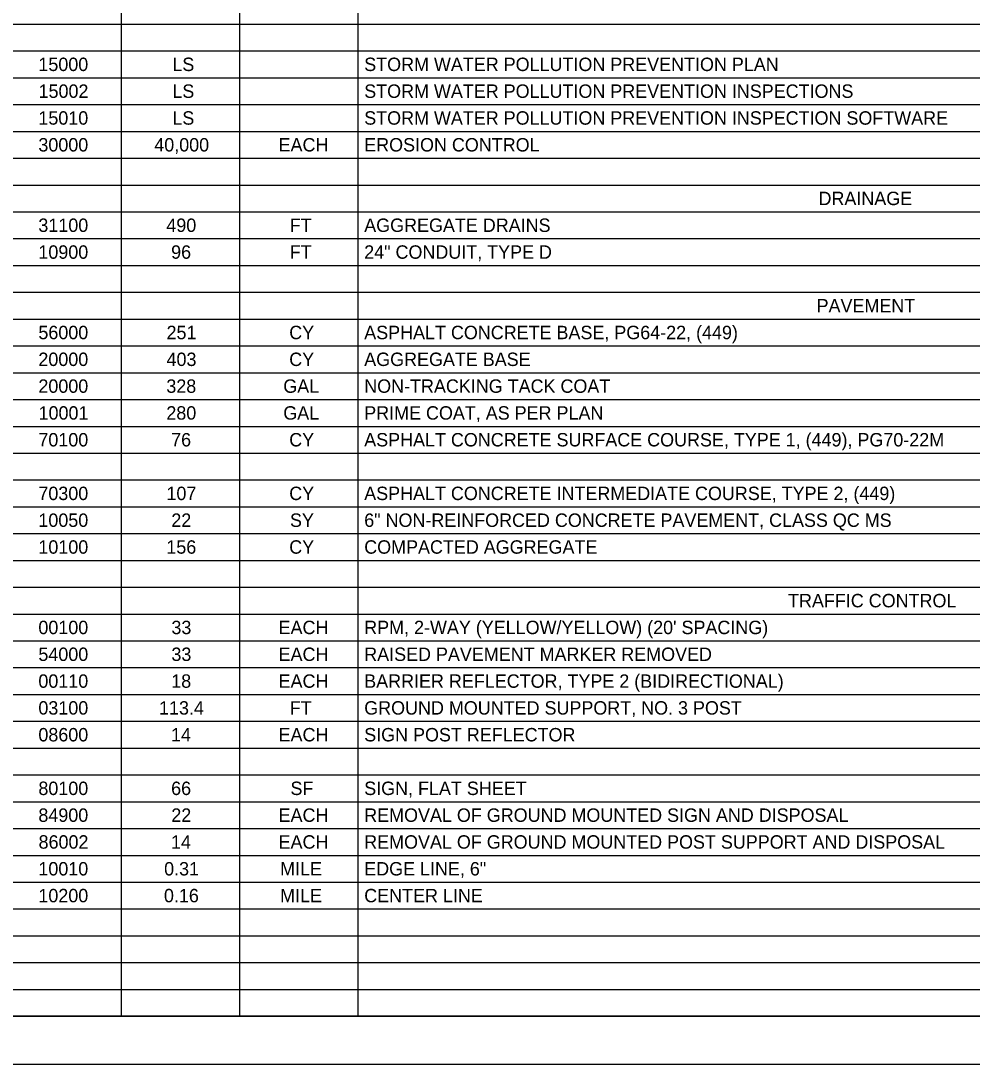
# Model space of a CAD drawing. Extents: x 0 to 34, y 0 to 22.
# Drawn here: x 16.99 to 26.92, y 0 to 10.89 of the extents above; entities that cross this region are included whole.
import ezdxf

# ---------------------------------------------------------------- set-up
doc = ezdxf.new("R2010")
doc.units = 0
for name, color, linetype in [('SH_Border', 7, 'Continuous'), ('SH_Cut_Line', 7, 'Continuous'), ('SH_Data', 7, 'Continuous'), ('SH_Text', 7, 'Continuous')]:
    doc.layers.add(name, color=color, linetype=linetype)

msp = doc.modelspace()

# ---------------------------------------------------------------- linework, layer by layer
at = {"layer": 'SH_Border'}
msp.add_lwpolyline([(1.5, 21.5), (33.5, 21.5), (33.5, 0.5), (1.5, 0.5)], close=True, dxfattribs=at)
at = {"layer": 'SH_Cut_Line'}
msp.add_lwpolyline([(0, 0), (34, 0), (34, 22), (0, 22)], close=True, dxfattribs=at)
at = {"layer": 'SH_Data'}
for p, q in [((18.036, 21.5), (18.036, 0.5)), ((19.272, 21.5), (19.272, 0.5)), ((20.507, 21.5), (20.507, 0.5)), ((1.5, 10.86), (32.004, 10.86)), ((1.5, 10.58), (32.004, 10.58)), ((1.5, 10.3), (32.004, 10.3)), ((1.5, 10.02), (32.004, 10.02)), ((1.5, 9.74), (32.004, 9.74)), ((1.5, 9.46), (32.004, 9.46)), ((1.5, 9.18), (32.004, 9.18)), ((1.5, 8.9), (32.004, 8.9)), ((1.5, 8.62), (32.004, 8.62)), ((1.5, 8.34), (32.004, 8.34)), ((1.5, 8.06), (32.004, 8.06)), ((1.5, 7.78), (32.004, 7.78)), ((1.5, 7.5), (32.004, 7.5)), ((1.5, 7.22), (32.004, 7.22)), ((1.5, 6.94), (32.004, 6.94)), ((1.5, 6.66), (32.004, 6.66)), ((1.5, 6.38), (32.004, 6.38)), ((1.5, 6.1), (32.004, 6.1)), ((1.5, 5.82), (32.004, 5.82)), ((1.5, 5.54), (32.004, 5.54)), ((1.5, 5.26), (32.004, 5.26)), ((1.5, 4.98), (32.004, 4.98)), ((1.5, 4.7), (32.004, 4.7)), ((1.5, 4.42), (32.004, 4.42)), ((1.5, 4.14), (32.004, 4.14)), ((1.5, 3.86), (32.004, 3.86)), ((1.5, 3.58), (32.004, 3.58)), ((1.5, 3.3), (32.004, 3.3)), ((1.5, 3.02), (32.004, 3.02)), ((1.5, 2.74), (32.004, 2.74)), ((1.5, 2.46), (32.004, 2.46)), ((1.5, 2.18), (32.004, 2.18)), ((1.5, 1.9), (32.004, 1.9)), ((1.5, 1.62), (32.004, 1.62)), ((1.5, 1.34), (32.004, 1.34)), ((1.5, 1.06), (32.004, 1.06)), ((1.5, 0.78), (32.004, 0.78)), ((1.5, 0.5), (32.004, 0.5))]:
    msp.add_line(p, q, dxfattribs=at)

# ---------------------------------------------------------------- texts
at = {"layer": 'SH_Text'}
for s, p in [('15000', (17.171, 10.37)), ('LS', (18.57, 10.37)), ('STORM WATER POLLUTION PREVENTION PLAN', (20.573, 10.37)), ('15002', (17.173, 10.09)), ('LS', (18.57, 10.09)), ('STORM WATER POLLUTION PREVENTION INSPECTIONS', (20.573, 10.09)), ('15010', (17.171, 9.81)), ('LS', (18.57, 9.81)), ('STORM WATER POLLUTION PREVENTION INSPECTION SOFTWARE', (20.573, 9.81)), ('30000', (17.171, 9.53)), ('40,000', (18.381, 9.53)), ('EACH', (19.679, 9.53)), ('EROSION CONTROL', (20.573, 9.53)), ('DRAINAGE', (25.316, 8.97)), ('31100', (17.171, 8.69)), ('490', (18.507, 8.69)), ('FT', (19.796, 8.69)), ('AGGREGATE DRAINS', (20.573, 8.69)), ('10900', (17.171, 8.41)), ('96', (18.557, 8.41)), ('FT', (19.796, 8.41)), ('24" CONDUIT, TYPE D', (20.573, 8.41)), ('PAVEMENT', (25.296, 7.85)), ('56000', (17.171, 7.57)), ('251', (18.509, 7.57)), ('CY', (19.79, 7.57)), ('ASPHALT CONCRETE BASE, PG64-22, (449)', (20.573, 7.57)), ('20000', (17.171, 7.29)), ('403', (18.509, 7.29)), ('CY', (19.79, 7.29)), ('AGGREGATE BASE', (20.573, 7.29)), ('20000', (17.171, 7.01)), ('328', (18.507, 7.01)), ('GAL', (19.728, 7.01)), ('NON-TRACKING TACK COAT', (20.573, 7.01)), ('10001', (17.173, 6.73)), ('280', (18.507, 6.73)), ('GAL', (19.728, 6.73)), ('PRIME COAT, AS PER PLAN', (20.573, 6.73)), ('70100', (17.171, 6.45)), ('76', (18.557, 6.45)), ('CY', (19.79, 6.45)), ('ASPHALT CONCRETE SURFACE COURSE, TYPE 1, (449), PG70-22M', (20.573, 6.45)), ('70300', (17.171, 5.89)), ('107', (18.508, 5.89)), ('CY', (19.79, 5.89)), ('ASPHALT CONCRETE INTERMEDIATE COURSE, TYPE 2, (449)', (20.573, 5.89)), ('10050', (17.171, 5.61)), ('22', (18.559, 5.61)), ('SY', (19.798, 5.61)), ('6" NON-REINFORCED CONCRETE PAVEMENT, CLASS QC MS', (20.573, 5.61)), ('10100', (17.171, 5.33)), ('156', (18.507, 5.33)), ('CY', (19.79, 5.33)), ('COMPACTED AGGREGATE', (20.573, 5.33)), ('TRAFFIC CONTROL', (24.998, 4.77)), ('00100', (17.171, 4.49)), ('33', (18.56, 4.49)), ('EACH', (19.679, 4.49)), ("RPM, 2-WAY (YELLOW/YELLOW) (20' SPACING)", (20.573, 4.49)), ('54000', (17.171, 4.21)), ('33', (18.56, 4.21)), ('EACH', (19.679, 4.21)), ('RAISED PAVEMENT MARKER REMOVED', (20.573, 4.21)), ('00110', (17.171, 3.93)), ('18', (18.558, 3.93)), ('EACH', (19.679, 3.93)), ('BARRIER REFLECTOR, TYPE 2 (BIDIRECTIONAL)', (20.573, 3.93)), ('03100', (17.171, 3.65)), ('113.4', (18.431, 3.65)), ('FT', (19.796, 3.65)), ('GROUND MOUNTED SUPPORT, NO. 3 POST', (20.573, 3.65)), ('08600', (17.171, 3.37)), ('14', (18.556, 3.37)), ('EACH', (19.679, 3.37)), ('SIGN POST REFLECTOR', (20.573, 3.37)), ('80100', (17.171, 2.81)), ('66', (18.557, 2.81)), ('SF', (19.803, 2.81)), ('SIGN, FLAT SHEET', (20.573, 2.81)), ('84900', (17.171, 2.53)), ('22', (18.559, 2.53)), ('EACH', (19.679, 2.53)), ('REMOVAL OF GROUND MOUNTED SIGN AND DISPOSAL', (20.573, 2.53)), ('86002', (17.173, 2.25)), ('14', (18.556, 2.25)), ('EACH', (19.679, 2.25)), ('REMOVAL OF GROUND MOUNTED POST SUPPORT AND DISPOSAL', (20.573, 2.25)), ('10010', (17.171, 1.97)), ('0.31', (18.484, 1.97)), ('MILE', (19.695, 1.97)), ('EDGE LINE, 6"', (20.573, 1.97)), ('10200', (17.171, 1.69)), ('0.16', (18.482, 1.69)), ('MILE', (19.695, 1.69)), ('CENTER LINE', (20.573, 1.69))]:
    msp.add_text(s, height=0.14, dxfattribs=at).set_placement(p)

doc.saveas('drawing.dxf')
